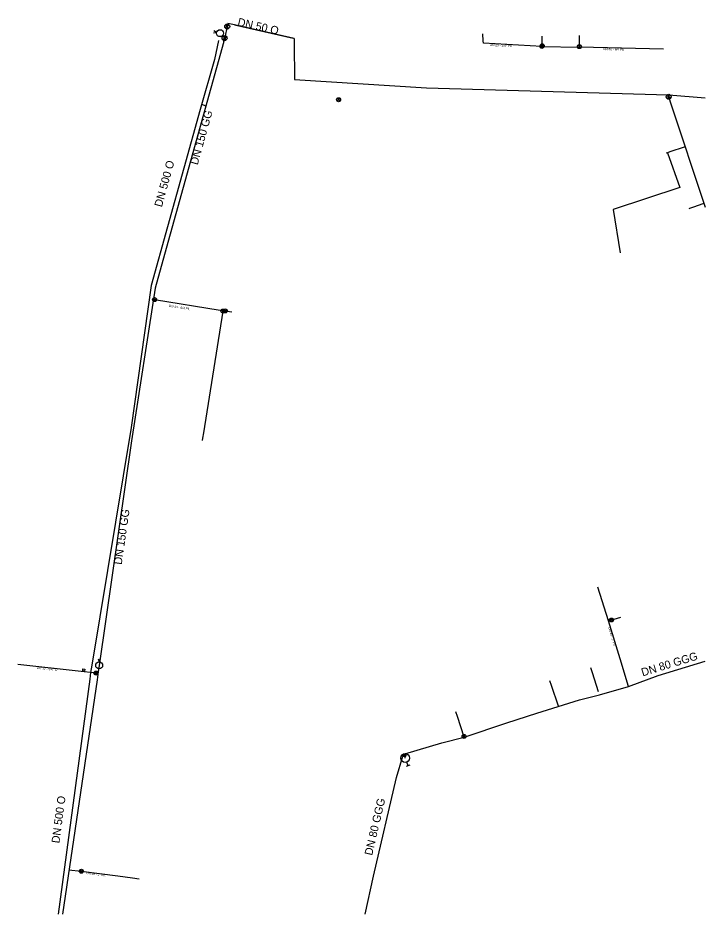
# Model space of a CAD drawing. Extents: x -444527 to -444390, y -1121150 to -1120970.
import ezdxf

# ---------------------------------------------------------------- set-up
doc = ezdxf.new("R2010")
doc.units = 0
for name, color, linetype in [('_hydrantova_odbocka_', 7, 'Continuous'), ('_pripojka_priblizne_', 7, 'Continuous'), ('_voda_smvak_prevzato_z_dokumentace_', 7, 'Continuous'), ('_vodovodni_chranicka_', 7, 'Continuous'), ('Default', 7, 'Continuous'), ('MoLevel 27', 7, 'Continuous'), ('MoLevel 28', 7, 'Continuous'), ('MoLevel 30', 7, 'Continuous'), ('MoLevel 32', 7, 'Continuous'), ('MoLevel 42', 7, 'Continuous'), ('MoLevel 46', 7, 'Continuous'), ('MoLevel 53', 7, 'Continuous'), ('MoLevel 60', 7, 'Continuous')]:
    doc.layers.add(name, color=color, linetype=linetype)

# ---------------------------------------------------------------- blocks, each defined once
blk = doc.blocks.new('_uzaver_')
at = {"layer": 'Default'}
for p, q in [((-0.000035, -0.000035), (0.000035, 0.000035)), ((0.000035, -0.000035), (-0.000035, 0.000035))]:
    blk.add_line(p, q, dxfattribs=at)
for radius in [0.00005, 0.0000025]:
    blk.add_circle((0, 0), radius, dxfattribs=at)
blk = doc.blocks.new('_uzaver_pripojka_')
at = {"layer": 'Default'}
for p, q in [((-0.000035, -0.000035), (0.000035, 0.000035)), ((0.000035, -0.000035), (-0.000035, 0.000035))]:
    blk.add_line(p, q, dxfattribs=at)
for radius in [0.00005, 0.0000025]:
    blk.add_circle((0, 0), radius, dxfattribs=at)
blk = doc.blocks.new('_hydrant_voda_')
at = {"layer": 'Default'}
for p, q in [((-0.000023, 0.000095), (0.000023, 0.000095)), ((0, 0.000095), (0, 0.00005))]:
    blk.add_line(p, q, dxfattribs=at)
blk.add_circle((0, 0), 0.00005, dxfattribs=at)
blk = doc.blocks.new('_sachta_voda_')
at = {"layer": 'Default'}
blk.add_lwpolyline([(-0.00001, 0.000065), (0, 0.000035), (0.00001, 0.000065)], dxfattribs=at)
blk.add_circle((0, 0), 0.000035, dxfattribs=at)
blk = doc.blocks.new('_poklop_voda_')
at = {"layer": 'Default'}
blk.add_lwpolyline([(-0.00002, 0.00002), (0.00002, 0.00002), (0.00002, -0.00002), (-0.00002, -0.00002), (-0.00002, 0.00002)], dxfattribs=at)

msp = doc.modelspace()

# ---------------------------------------------------------------- linework, layer by layer
at = {"layer": '_hydrantova_odbocka_'}
msp.add_lwpolyline([(-444449.9, -1121118.46), (-444449.99, -1121117.95), (-444449.98, -1121117.65)], dxfattribs=at)
at = {"layer": '_pripojka_priblizne_'}
for p, q in [((-444422.51, -1120975.74), (-444414.99, -1120975.92)), ((-444398.13, -1120976.33), (-444414.99, -1120975.92)), ((-444489.86, -1120987.76), (-444490.6, -1120987.38)), ((-444393.81, -1120995.86), (-444397.06, -1120996.97)), ((-444397.31, -1120997.07), (-444397.6, -1120997.16)), ((-444397, -1120996.95), (-444397.31, -1120997.07)), ((-444500.32, -1121026.49), (-444500.12, -1121026.53)), ((-444409.16, -1121090.97), (-444411.28, -1121084.18)), ((-444409.16, -1121090.97), (-444406.71, -1121090.24)), ((-444406.83, -1121098.6), (-444409.16, -1121090.97)), ((-444405.14, -1121104.1), (-444406.83, -1121098.6)), ((-444514.81, -1121101.11), (-444527.5, -1121099.68))]:
    msp.add_line(p, q, dxfattribs=at)
for points in [[(-444422.51, -1120975.74), (-444434.23, -1120975.13), (-444434.26, -1120974.66), (-444434.32, -1120973.22)], [(-444422.44, -1120975.74), (-444422.44, -1120975.63), (-444422.45, -1120975.25), (-444422.47, -1120973.71)], [(-444414.99, -1120975.92), (-444414.99, -1120974.93), (-444414.99, -1120973.53)], [(-444397.31, -1120997.07), (-444394.84, -1121004.04), (-444408.22, -1121008.48), (-444406.8, -1121017.14)], [(-444390.07, -1121007.22), (-444390.25, -1121007.29), (-444392.13, -1121007.98)], [(-444392.13, -1121007.98), (-444392.91, -1121008.27), (-444393.06, -1121008.34)], [(-444500.12, -1121026.53), (-444486.97, -1121028.66), (-444486.36, -1121028.69)], [(-444486.36, -1121028.69), (-444486.42, -1121028.82), (-444490.32, -1121053.22), (-444490.5, -1121054.34), (-444490.57, -1121054.75)], [(-444486.36, -1121028.69), (-444485.91, -1121028.78), (-444485.6, -1121028.83), (-444484.61, -1121028.98)], [(-444411.16, -1121105.2), (-444412.37, -1121101.35), (-444412.67, -1121100.4)], [(-444511.45, -1121101.49), (-444512.33, -1121101.39), (-444514.81, -1121101.11)], [(-444419.15, -1121108.09), (-444420.59, -1121103.9), (-444420.91, -1121102.95)], [(-444438.06, -1121114.29), (-444439.42, -1121110.13), (-444439.73, -1121109.18)], [(-444517.29, -1121140.91), (-444514.81, -1121141.15), (-444507.49, -1121142.1)], [(-444507.49, -1121142.1), (-444504.52, -1121142.49), (-444503.18, -1121142.7)]]:
    msp.add_lwpolyline(points, dxfattribs=at)
at = {"layer": '_voda_smvak_prevzato_z_dokumentace_'}
for p, q in [((-444472.13, -1120974.16), (-444484.1, -1120971.45)), ((-444485.56, -1120971.76), (-444486.05, -1120973.89)), ((-444486.25, -1120974.76), (-444498.43, -1121018.67)), ((-444487.12, -1120973.63), (-444486.05, -1120973.89)), ((-444486.25, -1120974.76), (-444486.1, -1120974.07)), ((-444486.1, -1120974.07), (-444486.05, -1120973.89)), ((-444397.07, -1120985.48), (-444397.1, -1120985.85)), ((-444397.1, -1120985.85), (-444396.77, -1120986.85)), ((-444397.07, -1120985.48), (-444389.81, -1120986.04)), ((-444396.77, -1120986.85), (-444389.81, -1121008.01)), ((-444513.12, -1121102.65), (-444519.42, -1121149.76)), ((-444511.65, -1121102.79), (-444518.6, -1121149.76))]:
    msp.add_line(p, q, dxfattribs=at)
for points in [[(-444484.1, -1120971.45), (-444485.42, -1120971.15), (-444485.56, -1120971.76)], [(-444487.31, -1120974.53), (-444488.14, -1120978.37), (-444490.98, -1120988.4), (-444500.77, -1121023.72), (-444504.83, -1121052.19), (-444512.7, -1121099.84)], [(-444472.13, -1120974.16), (-444472.15, -1120975.18), (-444472.09, -1120982.41), (-444445.6, -1120984.03), (-444397.17, -1120985.47), (-444397.07, -1120985.48)], [(-444498.43, -1121018.67), (-444499.97, -1121024.21), (-444504.74, -1121054.83), (-444511.22, -1121099.88)], [(-444449.96, -1121117.64), (-444442.55, -1121115.4), (-444438.05, -1121114.29), (-444429.56, -1121111.42), (-444423.52, -1121109.48), (-444414.95, -1121106.76), (-444410.99, -1121105.76), (-444405.14, -1121104.09), (-444399.2, -1121101.92), (-444389.81, -1121099.04)], [(-444512.7, -1121099.84), (-444512.94, -1121101.3), (-444513.12, -1121102.65)], [(-444511.22, -1121099.88), (-444511.41, -1121101.19), (-444511.65, -1121102.79)], [(-444457.9, -1121149.76), (-444456.23, -1121142.16), (-444451.64, -1121122.4), (-444450.4, -1121118.09), (-444450.2, -1121117.77), (-444449.96, -1121117.64)]]:
    msp.add_lwpolyline(points, dxfattribs=at)
at = {"layer": '_vodovodni_chranicka_'}
msp.add_line((-444484.09, -1120971.45), (-444472.37, -1120974.11), dxfattribs=at)

# ---------------------------------------------------------------- block references
at = {"layer": 'MoLevel 27'}
for p, xscale, yscale, rotation in [((-444485.56, -1120971.76), 10000, 10000.000000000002, 77.0138921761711), ((-444486.1, -1120974.07), 9999.999999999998, 10000, -103.02654722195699), ((-444397.1, -1120985.85), 10000, 9999.999999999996, -72.04057222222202), ((-444449.99, -1121117.95), 4999.999999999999, 4999.999999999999, -76.91126721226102)]:
    msp.add_blockref('_uzaver_', p, dxfattribs=dict(at, xscale=xscale, yscale=yscale, rotation=rotation))
at = {"layer": 'MoLevel 28', "xscale": 17636.684303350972, "yscale": 17636.684303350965, "rotation": -160.24735110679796}
msp.add_blockref('_hydrant_voda_', (-444449.9, -1121118.46), dxfattribs=at)
at = {"layer": 'MoLevel 30', "xscale": 20000, "yscale": 20000, "rotation": 77.7830125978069}
msp.add_blockref('_sachta_voda_', (-444487, -1120973.1), dxfattribs=at)
at = {"layer": 'MoLevel 30', "xscale": 20000, "yscale": 20000}
msp.add_blockref('_sachta_voda_', (-444511.22, -1121099.88), dxfattribs=at)
at = {"layer": 'MoLevel 42', "xscale": 10000, "yscale": 10000.000000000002, "rotation": -7.933271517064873}
msp.add_blockref('_poklop_voda_', (-444514.3, -1121100.8), dxfattribs=at)
at = {"layer": 'MoLevel 53'}
for p, xscale, yscale, rotation in [((-444422.51, -1120975.74), 8000, 7999.999999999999, -2.7742944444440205), ((-444422.44, -1120975.63), 7999.999999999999, 7999.999999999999, 90), ((-444414.99, -1120975.79), 7999.999999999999, 8000.000000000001, 90.0105161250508), ((-444500.12, -1121026.53), 7999.999999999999, 7999.999999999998, -9.22114854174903), ((-444408.56, -1121090.78), 7999.999999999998, 8000, 17.592425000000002), ((-444511.87, -1121101.44), 8000, 7999.999999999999, -8.544593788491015), ((-444438.11, -1121114.13), 7999.999999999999, 8000.000000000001, -71.94893611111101), ((-444514.79, -1121141.16), 8000, 8000, -7.31269810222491)]:
    msp.add_blockref('_uzaver_pripojka_', p, dxfattribs=dict(at, xscale=xscale, yscale=yscale, rotation=rotation))
at = {"layer": 'MoLevel 53', "xscale": 7999.999999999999, "yscale": 7999.999999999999}
for p in [(-444463.24, -1120986.44), (-444486.42, -1121028.82), (-444485.91, -1121028.78)]:
    msp.add_blockref('_uzaver_pripojka_', p, dxfattribs=at)

# ---------------------------------------------------------------- texts
at = {"layer": 'MoLevel 32'}
for s, rotation, p in [("DN 20 - 3/4'' PE", 357.0198, (-444432.93, -1120975.65)), ('DN 40 - 6/4 PE', 358.6196, (-444410.24, -1120976.49)), ('DN 40 - 6/4 PE', 350.7789, (-444497.26, -1121027.98)), ("DN 50 - 2'' PE", 287.0107, (-444409.23, -1121092.3)), ("DN 32 - 5/4'' O", 353.5761, (-444523.72, -1121100.57)), ("DN 25 - 1'' PE", 352.5876, (-444513.86, -1121141.73))]:
    msp.add_text(s, height=0.455, rotation=rotation, dxfattribs=at).set_placement(p)
at = {"layer": 'MoLevel 46'}
for s, rotation, p in [('DN 150 GG', 74.5001, (-444491.48, -1120999.62)), ('DN 500 O', 74.5115, (-444498.66, -1121008.08)), ('DN 150 GG', 81.8198, (-444506.71, -1121079.76)), ('DN 80 GGG', 17.0595, (-444402.31, -1121102.1)), ('DN 500 O', 82.3874, (-444519.2, -1121135.63)), ('DN 80 GGG', 76.9228, (-444456.52, -1121138.1))]:
    msp.add_text(s, height=1.605, rotation=rotation, dxfattribs=at).set_placement(p)
at = {"layer": 'MoLevel 60'}
msp.add_text('DN 50 O', height=1.605, rotation=347.1945, dxfattribs=at).set_placement((-444483.59, -1120971.56))

doc.saveas('drawing.dxf')
